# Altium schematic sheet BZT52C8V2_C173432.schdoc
size 127 x 101 mm
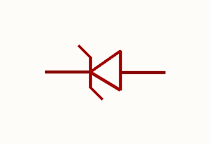
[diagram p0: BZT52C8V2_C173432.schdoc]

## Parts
D?  bzt52c8v2_c173432  [SOD-123_L2.8-W1.8-LS3.7-RD]  (value not drawn)

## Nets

Not connected (* = marked no-connect by the designer): D? 1 2

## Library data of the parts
D? = bzt52c8v2_c173432: 二极管配置:1个独立式;稳压值(标称值):8.2V;稳压值(范围值):7.79V~8.61V;耗散功率(Pd):500mW;; Manufacturer: MDD(辰达半导体); AddInBom: yes; ModelId: 7884390a25fb4c08947731ebfba7e3f8; ModelTransform: 144.8816,62.992,0,0,0,0,0,0,0; Diode Configuration: 1个独立式; Zener Voltage(Nom): 8.2V; Reverse Leakage Current (Ir): 500nA; Pd - Power Dissipation: 500mW; Impedance(Zzt): 30Ω; Tolerance: ±5%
